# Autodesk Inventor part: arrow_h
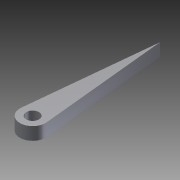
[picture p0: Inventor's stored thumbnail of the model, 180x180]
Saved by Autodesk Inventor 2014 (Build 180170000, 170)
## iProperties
Created: 2013-08
Part Number: arrow_h
Material: Сталь, ковкая
Document SubType Name: Modeling
Designer: ed
Density: 1 g/cm^3
Appearance: Сталь
Author: ed
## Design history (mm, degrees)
sketch "Эскиз1"
  geometry: L1 (-9.95, 1)-(0, 100); L2 (0, 100)-(9.95, 1); L3 (0, 0)-(0, 53.426); C1 r 5 at (0, 0); A1 r 10 centre (0, 0) between (-9.95, 1) and (9.95, 1); 1 further point
  constraints: 6 end point, 2 centre point, 2 coincident, 2 point on circle, 2 tangent, 1 vertical, 1 other
  dimensions: "d0" = 20 diameter of A1; "d1" = 10 diameter of C1; "d2" = 100 distance of L1.end point (0, 0)
extrude "Выдавливание1" new body sketch "Эскиз1" distance "d3" = 10; taper "d4" = 0 deg
node "Твердое тело1"
